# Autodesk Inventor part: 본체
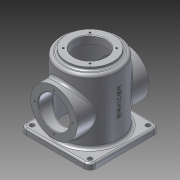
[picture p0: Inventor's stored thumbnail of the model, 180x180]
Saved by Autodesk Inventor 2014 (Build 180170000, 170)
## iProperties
Created: 2015-10
Part Number: 본체
Material: Aluminum 6061
Document SubType Name: Modeling
Designer: user
Mass: 983.87 g
Surface Area: 1075.04 cm^2
Volume: 363.051 cm^3
Density: 2.71 g/cm^3
Appearance: Aluminum - Flat
Author: user
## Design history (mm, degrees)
sketch "Sketch1"
  geometry: L1 (-60, -60)-(60, -60); L2 (60, -60)-(60, 60); L3 (60, 60)-(-60, 60); L4 (-60, 60)-(-60, -60); L5 (-60, -60)-(60, 60); L6 (60, -60)-(-60, 60); 1 further point
  constraints: 12 end point, 2 midpoint, 2 parallel, 1 horizontal, 1 perpendicular
  dimensions: "d0" = 120 distance of L3.end L2.end; "d1" = 120 distance of L2.end L1.end
extrude "Extrusion1" new body sketch "Sketch1" distance "d2" = 10; taper "d3" = 0 deg
sketch "Sketch2"
  geometry: C1 r 50 at (0, 0); 1 further point
  constraints: 1 centre point, 1 coincident
  dimensions: "d4" = 100 diameter of C1
extrude "Extrusion2" join sketch "Sketch2" distance "d5" = 110; taper "d6" = 0 deg
sketch "Sketch3"
  geometry: C1 r 50 at (0, 0) reference; C2 r 40 at (0, 0)
  constraints: 1 centre point, 1 coincident
  dimensions: "d7" = 80 diameter of C2
extrude "Extrusion3" join sketch "Sketch3" distance "d8" = 5; taper "d9" = 0 deg
sketch "Sketch4"
  geometry: C1 r 40 at (0, 60); 1 further point
  constraints: 1 centre point, 1 vertical alignment
  dimensions: "d10" = 80 diameter of C1; "d11" = 60 distance of point (0, 0) C1.centre
extrude "Extrusion4" join sketch "Sketch4" stored distance "d12" = 124; taper "d13" = 0 deg
sketch "Sketch5"
  geometry: C1 r 40 at (0, 0) reference; C2 r 27 at (0, 0)
  constraints: 1 centre point, 1 coincident
  dimensions: "d14" = 54 diameter of C2
extrude "Extrusion5" cut sketch "Sketch5" stored distance "d15" = 0; taper "d16" = 0 deg
sketch "Sketch6"
  geometry: C1 r 40 at (0, 0) reference; C2 r 27 at (0, 0); 1 further point
  constraints: 1 centre point, 1 coincident
  dimensions: "d17" = 54 diameter of C2
extrude "Extrusion6" cut sketch "Sketch6" stored distance "d18" = 0; taper "d19" = 0 deg
sketch "Sketch7"
  geometry: C1 r 27 at (0, 0) reference; C2 r 45 at (0, 0)
  constraints: 1 centre point, 1 coincident
  dimensions: "d20" = 90 diameter of C2
extrude "Extrusion7" cut sketch "Sketch7" distance "d21" = 112; taper "d22" = 0 deg
fillet "Fillet1" dims "d23" = 10
chamfer "Chamfer1" distance "d24" = 3; stored, may be unused: second distance "d25" = 2, angle "d26" = 45 deg
sketch "Sketch8"
  geometry: L1 (60, -50)-(60, 50) reference; L2 (-50, -60)-(50, -60) reference; C1 r 4 at (50, -50)
  constraints: 1 centre point
  dimensions: "d27" = 8 diameter of C1; "d28" = 10 distance from line of L1 C1.centre; "d29" = 10 distance from line of L2 C1.centre
extrude "Extrusion8" cut sketch "Sketch8" stored distance "d30" = 0; taper "d31" = 0 deg
pattern_linear "Rectangular Pattern1" dims "d34" = 100
sketch "Sketch9"
  geometry: L1 (-32.5, 0)-(32.5, 0); L2 (40, 62)-(-40, 62) reference; L3 (22.981, 22.981)-(-22.981, -22.981); C1 r 40 at (0, 0) reference; A1 r 32.5 centre (0, 0) between (-32.5, 0) and (32.5, 0); 2 further points
  constraints: 4 end point, 4 point on circle, 3 midpoint, 2 coincident, 1 centre point, 1 horizontal
  dimensions: "d38" = 65 diameter of A1; "d39" = 45 deg angle of L3 L1
hole "Hole1" sketch "Sketch9" at (22.981, 22.981) diameter "d40" = 3.242; stored, may be unused: countersink angle "d44" = 90 deg, drill point angle "d46" = 118 deg; dims "d41" = 8, "d42" = 4, "d43" = 2, "d45" = 10
pattern_circular "Circular Pattern1" dims angle "d48" = 360 deg
sketch "Sketch10"
  geometry: C1 r 27 at (0, 0) reference; 2 further points
  constraints: 1 horizontal alignment
  dimensions: "d50" = 32.5 distance of C1.centre point (32.5, 0)
hole "Hole2" sketch "Sketch10" at (32.5, 0) diameter "d51" = 3.242; stored, may be unused: countersink angle "d55" = 90 deg, drill point angle "d57" = 118 deg; dims "d52" = 8, "d53" = 4, "d54" = 2, "d56" = 10
pattern_circular "Circular Pattern2" dims angle "d59" = 360 deg
mirror "Mirror1"
workplane "Work Plane1"
sketch "Sketch11" dims "d0" = 120, "d1" = 120, "d10" = 80, "d11" = 60
  geometry: L1 (-50, 0)-(50, 0) reference; 3 further points
  constraints: 1 midpoint, 1 vertical alignment, 1 other
  dimensions: "d62" = 70 distance from line of point (0, 70) L1
emboss "Emboss1" sketch "Sketch11" dims "d0" = 120, "d1" = 120, "d10" = 80, "d11" = 60, "d63" = 0.5, "d64" = 0
fillet "Fillet2" dims "d65" = 3
fillet "Fillet3" dims "d66" = 3
fillet "Fillet5" dims "d68" = 5
fillet "Fillet7" dims "d70" = 3
chamfer "Chamfer2" distance "d71" = 1; stored, may be unused: second distance "d72" = 2, angle "d73" = 45 deg
fillet "Fillet9" dims "d75" = 5
chamfer "Chamfer3" distance "d76" = 1; stored, may be unused: second distance "d77" = 2, angle "d78" = 45 deg
fillet "Fillet10" dims "d79" = 5
fillet "Fillet11" dims "d80" = 3
body "Solid1"
